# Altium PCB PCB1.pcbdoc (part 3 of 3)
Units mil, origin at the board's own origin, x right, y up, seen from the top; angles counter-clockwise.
Board outline 8664.15 x 6684.89 mil, 2 copper layers (Top Layer, Bottom Layer); 317 components, 306 nets, 1008 pads, 181 vias.
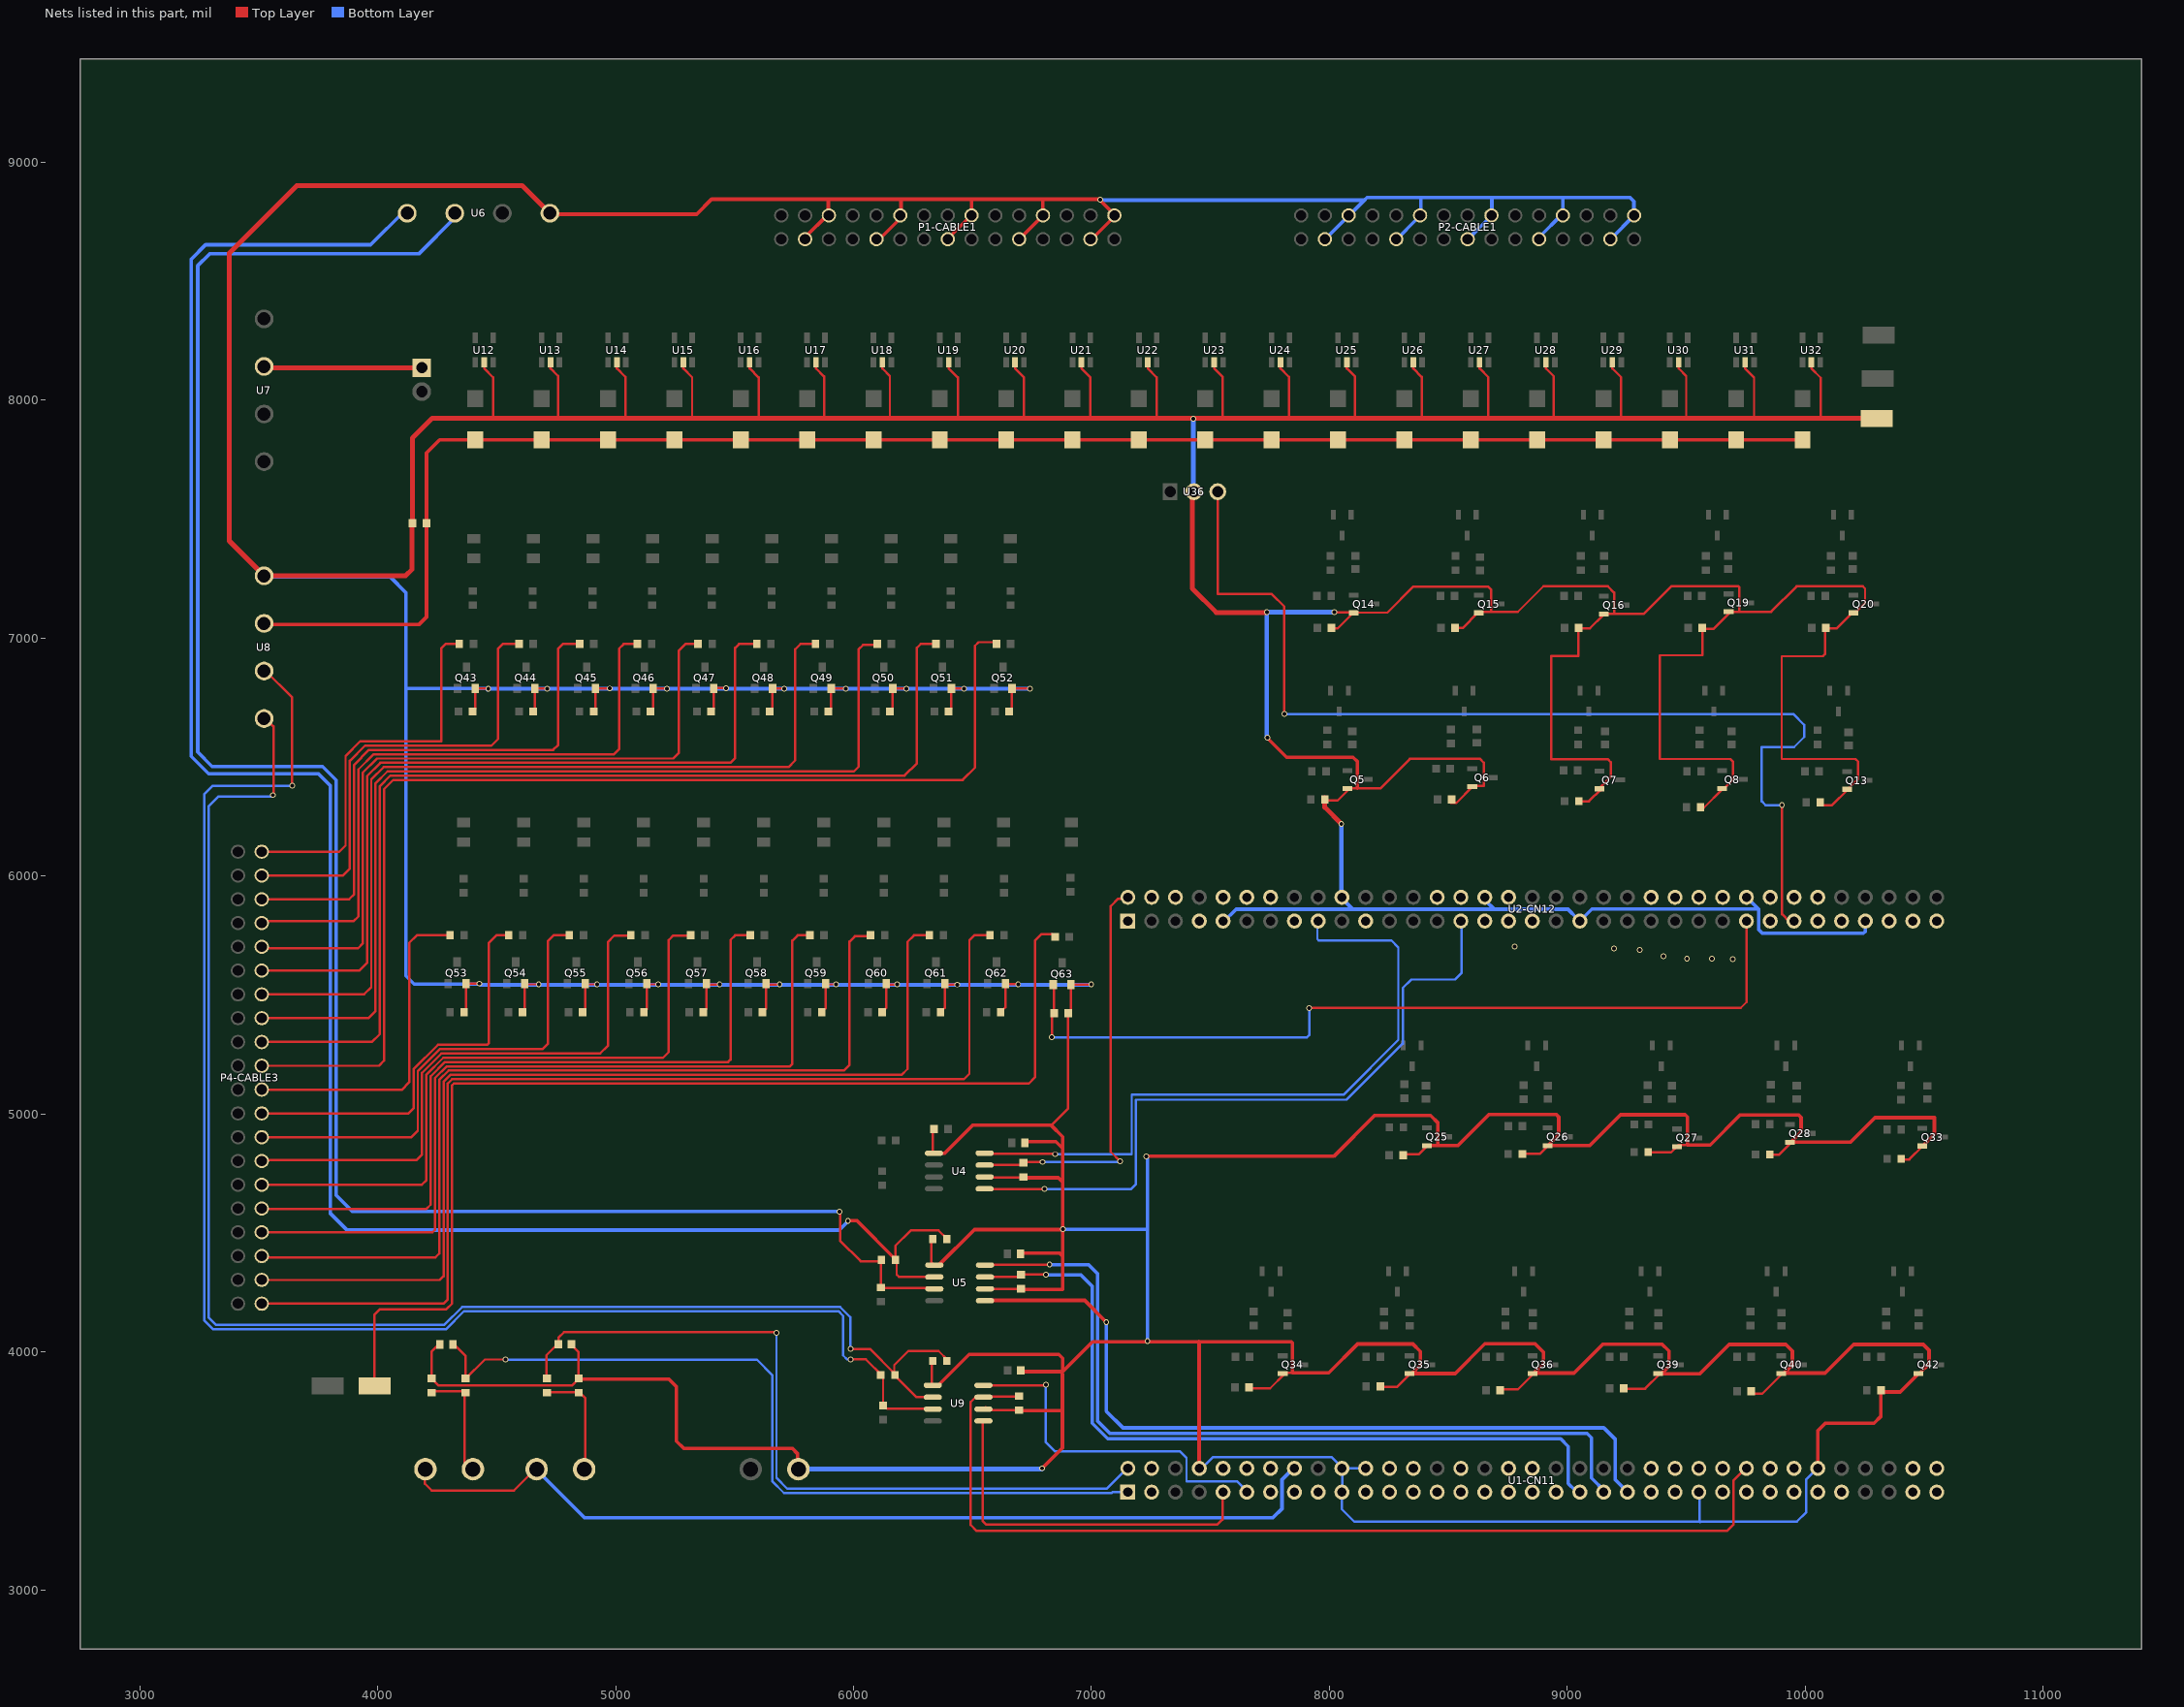
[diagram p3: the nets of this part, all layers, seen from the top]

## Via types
v1: diameter 24.02, hole 16, Top Layer to Bottom Layer, 181 vias

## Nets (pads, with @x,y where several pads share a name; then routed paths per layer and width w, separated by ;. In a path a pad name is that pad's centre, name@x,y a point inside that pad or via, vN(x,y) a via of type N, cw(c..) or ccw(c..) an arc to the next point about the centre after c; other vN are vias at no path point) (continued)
DO21: Q63.1 R126.2 U2-CN12.53 | length 3607.6
  Top Layer w10: v1@6833.62,5324.44 6834.26,5325.09 R126.2@6834.26,5427.61 ; Q63.1@6839.51,5544.34 6843.32,5540.53 R126.2@6843.32,5424.26 ; v1(7915.05,5445.54) 7915.71,5446.2 9729.52,5446.2 9754.1,5470.78 U2-CN12.53@9754.1,5796.94 ; U2-CN12.53@9749.58,5814.58 U2-CN12.53@9753.9,5810.26
  Bottom Layer w10: v1(6834.26,5323.16) 6835.39,5322.04 7905.61,5322.04 7916.92,5333.35 7916.92,5443.67 v1(7915.05,5445.54)
GND: C22.2 C23.2 C24.2 C25.2 C26.2 CN3.1 P1-CABLE1.3 P1-CABLE1.6 P1-CABLE1.9 P1-CABLE1.12 P1-CABLE1.15 P1-CABLE1.18 P1-CABLE1.21 P1-CABLE1.24 P1-CABLE1.27 P1-CABLE1.30 P2-CABLE1.3 P2-CABLE1.6 P2-CABLE1.9 P2-CABLE1.12 P2-CABLE1.15 P2-CABLE1.18 P2-CABLE1.21 P2-CABLE1.24 P2-CABLE1.27 P2-CABLE1.30 Q5.2 Q6.2 Q7.2 Q8.2 Q13.2 Q14.2 Q15.2 Q16.2 Q19.2 Q20.2 Q25.2 Q26.2 Q27.2 Q28.2 Q33.2 Q34.2 Q35.2 Q36.2 Q39.2 Q40.2 Q42.2 Q43.2 Q44.2 Q45.2 Q46.2 Q47.2 Q48.2 Q49.2 Q50.2 Q51.2 Q52.2 Q53.2 Q54.2 Q55.2 Q56.2 Q57.2 Q58.2 Q59.2 Q60.2 Q61.2 Q62.2 Q63.2 R9.1 R10.1 R11.1 R12.1 R21.1 R22.1 R23.1 R24.1 R29.1 R30.1 R39.1 R40.1 R41.1 R42.1 R51.1 R52.1 R53.1 R54.1 R59.1 R60.1 R63.1 R74.1 R75.1 R76.1 R77.1 R78.1 R89.1 R90.1 R91.1 R92.1 R93.1 R104.1 R105.1 R106.1 R107.1 R108.1 R119.1 R120.1 R121.1 R122.1 R123.1 R126.1 R129.1 R130.1 R133.1 R134.1 R136.1 R138.1 R141.1 R142.1 R143.1 U1-CN11.8 U1-CN11.19 U1-CN11.20 U1-CN11.22 U1-CN11.49 U1-CN11.60 U2-CN12.9 U2-CN12.20 U2-CN12.32 U2-CN12.39 U2-CN12.54 U2-CN12.63 U3.2 U4.2 U4.5 U5.2 U5.5 U6.4 U8.4 U9.2 U9.5 U12.2 U13.2 U14.2 U15.2 U16.2 U17.2 U18.2 U19.2 U20.2 U21.2 U22.2 U23.2 U24.2 U25.2 U26.2 U27.2 U28.2 U29.2 U30.2 U31.2 U32.2 U36.2 | length 72804.7
  Top Layer w10: U8.4@3522.95,7262.24 U8.4@3523.74,7261.45 ; R141.1@4225.92,3890.5 4225.92,4000.31 C25.2@4262.95,4037.34 ; R141.1@4229.24,3885.15 4256.05,3858.34 4815.97,3858.34 R142.1@4845.97,3888.34 ; R104.1@4363.26,5428.19 4371,5435.93 Q53.2@4371,5548.27 v1@4427.85,5548.27 ; R74.1@4398.7,6691.97 4410.37,6703.64 Q43.2@4410.37,6788.43 4463.95,6788.43 v1@4465.74,6786.64 ; U12.2@4447.78,8160.48 4447.78,8133.82 4485.35,8096.25 4485.35,7924.26 ; R105.1@4608.64,5428.19 4617.72,5437.27 Q54.2@4617.72,5548.27 4621.14,5544.85 v1@4678.12,5544.85 ; R75.1@4653.28,6691.97 4661.03,6699.71 Q44.2@4661.03,6788.43 4709.75,6788.43 v1@4711.8,6790.48 ; U13.2@4726.72,8160.48 4726.72,8133.82 4758.32,8102.22 4758.32,7924.26 ; C26.2@4818.52,4024.65 4844.38,3998.79 R142.1@4844.38,3892.49 ; R106.1@4861.9,5428.19 4872.31,5438.6 Q55.2@4872.31,5548.27 4875.73,5544.85 v1@4921.05,5544.85 ; R76.1@4907.88,6691.97 4915.62,6699.71 Q45.2@4915.62,6788.43 4969.53,6788.43 v1@4970.36,6787.6 ; U14.2@5005.66,8160.48 5005.66,8133.82 5041.55,8097.93 5041.55,7924.26 ; R107.1@5119.1,5428.19 5130.84,5439.93 Q56.2@5130.84,5548.27 5134.12,5544.99 v1@5179.78,5544.99 ; R77.1@5146.72,6691.97 5158.4,6703.65 Q46.2@5158.4,6788.43 5212.71,6788.43 v1@5213.54,6787.6 ; U15.2@5284.59,8160.48 5284.59,8133.82 5321.79,8096.63 5321.79,7924.26 ; R108.1@5368.43,5428.19 5381.5,5441.26 Q57.2@5381.5,5548.27 5385.17,5544.6 v1@5437.94,5544.6 ; R78.1@5401.32,6691.97 5412.99,6703.65 Q47.2@5412.99,6788.43 5416.01,6791.44 v1@5463.44,6791.44 ; U16.2@5563.53,8160.48 5563.53,8133.82 5601.27,8096.08 5601.27,7924.26 ; R119.1@5617.75,5428.19 5632.15,5442.6 Q58.2@5632.15,5548.27 5635.99,5544.44 v1(5689.64,5544.44) ; R89.1@5648.04,6691.97 5659.71,6703.65 Q48.2@5659.71,6788.43 5707.71,6788.43 v1@5709.5,6786.64 ; U17.2@5842.47,8160.48 5842.47,8133.82 5876.17,8100.12 5876.17,7924.26 ; R120.1@5867.07,5428.19 5882.81,5443.93 Q59.2@5882.81,5548.27 ; Q59.2@5888.15,5542.93 5890.05,5544.83 v1@5926.83,5544.83 ; R90.1@5894.75,6691.97 5906.43,6703.65 Q49.2@5906.43,6788.43 5967.71,6788.43 v1@5968.49,6789.2 ; R121.1@6120.33,5428.19 6137.4,5445.26 Q60.2@6137.4,5545.65 ; U18.2@6121.4,8160.48 6121.4,8133.82 6152.99,8102.24 6152.99,7924.26 ; Q60.2@6137.93,5546.17 Q60.2@6137.4,5545.65 ; R91.1@6153.28,6691.97 6164.96,6703.65 Q50.2@6164.96,6788.43 6165.63,6789.09 6220.31,6789.09 v1@6223.73,6785.67 ; v1@6182.78,5544.7 6138.35,5544.7 Q60.2@6137.4,5545.65 ; R134.1@6327.01,4471.34 6327.01,4377.49 U5.5@6341.37,4363.12 ; U9.5@6328.46,3863.83 R138.1@6328.46,3960.56 ; U4.5@6332.9,4837.31 6332.9,4933.08 R133.1@6341.83,4942.02 ; R122.1@6365.72,5428.19 6384.12,5446.59 Q61.2@6384.12,5545.41 ; Q61.2@6384.42,5545.71 Q61.2@6384.12,5545.41 ; R92.1@6400,6691.97 6411.68,6703.65 Q51.2@6411.68,6788.43 v1@6460.05,6788.43 ; U19.2@6400.34,8160.48 6400.34,8133.82 6438.46,8095.71 6438.46,7924.26 ; v1@6431.43,5544.28 6385.26,5544.28 Q61.2@6384.12,5545.41 ; U9.2@6555.9,3767.79 6547.28,3759.17 6551.11,3755.34 R136.1@6695.72,3755.34 ; U4.2@6564.01,4732.61 6718.13,4732.61 6722.74,4732.61 R129.1@6725.29,4735.16 ; U5.2@6569.16,4263.91 6696.21,4263.91 R130.1@6696.85,4264.55 ; R123.1@6618.98,5428.19 6638.72,5447.93 Q62.2@6638.72,5548.27 ; Q62.2@6644.47,5542.52 6647.12,5545.18 v1@6693.37,5545.18 ; R93.1@6654.6,6691.97 6666.28,6703.65 Q52.2@6666.28,6788.43 v1@6740.98,6788.43 ; U20.2@6679.28,8160.48 6679.28,8133.82 6715.5,8097.6 6715.5,7924.26 ; 6830.7,4951.63 6831.23,4952.16 6902.64,5023.57 R126.1@6902.64,5424.26 6914.32,5435.94 Q63.2@6914.32,5544.34 v1@6999.35,5544.34 ; 6876.91,3910.77 6879.46,3913.33 6879.46,3916.85 ; 6879.06,4855.75 6879.06,4835.38 6879.46,4834.98 6880.02,4834.42 ; U21.2@6958.22,8160.48 6958.22,8133.82 6995.94,8096.1 6995.94,7924.26 ; U22.2@7237.15,8160.48 7237.15,8133.82 7274.68,8096.3 7274.68,7924.26 ; U23.2@7516.09,8160.48 7516.09,8133.82 7552.14,8097.77 7552.14,7924.26 ; R52.1@7668.77,3849.47 7671.62,3846.62 7751.13,3846.62 Q34.2@7810.73,3906.21 ; U24.2@7795.03,8160.48 7795.03,8133.82 7830.24,8098.61 7830.24,7924.26 ; Q34.2@7806.09,3912.44 7845.23,3912.44 ; R9.1@7981.27,6317.81 8034.61,6317.81 Q5.2@8079.31,6362.5 ; R22.1@8007.85,7041.06 8035.41,7041.06 Q14.2@8095.64,7101.3 ; v1(8022.01,7108.97) 8101.39,7108.97 8102.78,7107.58 8244.18,7107.58 8353.99,7217.39 8667.16,7217.39 8681.2,7203.35 8681.2,7110.45 ; U25.2@8073.96,8160.48 8073.96,8133.82 8108.34,8099.45 8108.34,7924.26 ; Q5.2@8078.48,6367.27 8081.04,6369.82 8117.67,6369.82 8216.31,6369.82 8338.89,6492.4 8633.92,6492.4 8649.88,6476.44 8649.88,6378.12 8648.61,6379.4 Q6.2@8603.28,6379.4 ; R53.1@8211.54,3852.39 8284.59,3852.39 Q35.2@8341.27,3909.08 ; R39.1@8322.09,4830.55 8375.91,4830.55 Q25.2@8408.38,4863.02 ; Q35.2@8340.02,3909.08 Q35.2@8341.27,3909.08 ; Q35.2@8344.18,3911.98 Q35.2@8341.27,3909.08 ; Q35.2@8345.31,3906.67 8347.71,3909.08 Q35.2@8341.27,3909.08 ; U26.2@8352.9,8160.48 8352.9,8133.82 8388.36,8098.36 8388.36,7924.26 ; R10.1@8510.4,6307.71 8534.42,6307.71 Q6.2@8602.67,6375.96 ; R23.1@8526.25,7042.99 8560.85,7042.99 Q15.2@8624.93,7107.06 ; Q15.2@8621.43,7109.18 8622.71,7110.45 8681.2,7110.45 ; U27.2@8631.84,8160.48 8631.84,8133.82 8669.02,8096.64 8669.02,7924.26 ; R54.1@8728.65,3842.77 8793.05,3842.77 Q36.2@8860.33,3910.06 ; R40.1@8819.28,4832.37 8884.64,4832.37 Q26.2@8915.4,4863.12 ; Q36.2@8857.99,3910.89 8860.87,3910.89 Q36.2@8860.01,3910.04 ; U28.2@8910.78,8160.48 8910.78,8133.82 8943.85,8100.75 8943.85,7924.26 ; R24.1@9040.4,7045.08 9046.78,7038.69 9046.78,6925.69 8932.98,6925.69 8932.98,6491.95 9169.61,6491.95 9182.68,6478.88 9182.68,6416.82 Q7.2@9133.53,6367.67 ; R24.1@9045.28,7041.06 9095.26,7041.06 Q16.2@9152.29,7098.09 ; R11.1@9050.21,6314.45 9091.22,6314.45 9143.45,6366.67 Q7.2@9143.45,6360.9 ; Q16.2@9157.08,7102.15 9157.72,7101.52 9197.3,7101.52 ; U29.2@9189.71,8160.48 9189.71,8133.82 9226.43,8097.1 9226.43,7924.26 ; R59.1@9239.03,3845.66 9327.46,3845.66 Q39.2@9387.05,3905.25 ; R41.1@9336.86,4838.88 9437.09,4838.88 Q27.2@9465.18,4866.97 ; U30.2@9468.65,8160.48 9468.65,8133.82 9500.26,8102.21 9500.26,7924.26 ; Q27.2@9468.7,4869.85 9505.42,4869.85 ; R12.1@9552.36,6287.61 9574.47,6287.61 Q8.2@9653.28,6366.43 ; R29.1@9569.95,7040.17 9616.09,7040.17 Q19.2@9681.45,7105.53 ; R29.1@9571.26,7044.79 9569.34,7042.88 9569.34,6928.31 9389.2,6928.31 9389.2,6492.17 9685.01,6492.17 9697.59,6479.59 9697.59,6405.98 Q8.2@9653.54,6361.92 ; Q19.2@9678.68,7113.01 9680.6,7111.09 9724.01,7111.09 ; U31.2@9747.59,8160.48 9747.59,8133.82 9785.57,8095.84 9785.57,7924.26 ; R60.1@9772.48,3824.51 9819.58,3824.51 Q40.2@9903.2,3908.13 ; R42.1@9850.25,4829.28 9890.83,4829.28 Q28.2@9942.09,4880.54 ; Q28.2@9937.95,4879.42 9944.17,4885.65 Q28.2@9943.21,4886.61 ; U32.2@10026.52,8160.48 10026.52,8133.82 10065.89,8094.45 10065.89,7924.26 ; R21.1@10068.44,6297.94 10113.3,6297.94 Q13.2@10179.94,6364.58 ; R30.1@10084.24,7048.45 10084.24,6934.18 10074.24,6924.18 9901.59,6924.18 9901.59,6492.17 10212.03,6492.17 10223.34,6480.85 10223.34,6408.85 Q13.2@10177.38,6362.88 ; R30.1@10087.07,7042.16 10133.2,7042.16 Q20.2@10196.64,7105.59 ; Q20.2@10209.86,7105.98 10252,7148.12 10252,7208.49 10242.78,7217.71 9964.07,7217.71 9857.45,7111.09 9724.01,7111.09 ; R63.1@10316.03,3831.72 R63.1@10318.38,3831.72 ; R51.1@10401.37,4809.15 10437.9,4809.15 Q33.2@10495.57,4866.82 ; 8681.2,7110.45 8792.53,7110.45 8900.43,7218.35 9170.49,7218.35 9197.3,7191.53 9197.3,7101.52 ; 9197.3,7101.52 9321.16,7101.52 9438.63,7218.99 9718.27,7218.99 9724.01,7213.24 9724.01,7111.09
  Top Layer w15: U6.4@4716.61,8780.8 4718.05,8782.24 5340.89,8782.24 5403.85,8845.2 5892.18,8845.2 ; R142.1@4850.79,3885.96 5223.8,3885.96 5255.88,3853.87 5255.88,3624.93 5286.95,3593.87 5743.3,3593.87 5764.4,3572.77 5764.4,3510.55 U3.2@5759.61,3505.77 ; P1-CABLE1.3@5785.01,8680.84 5792.22,8680.84 P1-CABLE1.6@5896.03,8784.65 ; 5891.22,8846.16 5892.18,8845.2 ; P1-CABLE1.6@5894.1,8785.61 5894.1,8843.28 5892.18,8845.2 ; P1-CABLE1.9@6092.11,8669.3 6100.76,8669.3 P1-CABLE1.12@6194.47,8763.02 ; P1-CABLE1.12@6193.99,8777.92 6199.76,8783.68 6199.76,8837.51 ; U4.5@6354.3,4839.36 6358.97,4834.69 6383.04,4834.69 6501.52,4953.17 6830.22,4953.17 6831.23,4952.16 6879.06,4904.33 6879.06,4855.75 ; U9.5@6355.79,3854.67 6355.79,3859.01 6486.28,3989.5 6862.61,3989.5 6879.46,3972.64 6879.46,3916.85 ; U5.5@6357.25,4363.24 6509.19,4515.19 ; P1-CABLE1.15@6386.61,8669.3 6492.58,8775.27 P1-CABLE1.18@6502.29,8775.27 ; P1-CABLE1.18@6504.45,8777.44 P1-CABLE1.18@6502.29,8775.27 ; P1-CABLE1.18@6507.33,8770.23 P1-CABLE1.18@6502.29,8775.27 ; 6510.41,4513.97 v1@6879.46,4513.97 ; R136.1@6682.96,3752.49 6878.47,3752.49 ; P1-CABLE1.21@6687.55,8693.81 6713.51,8693.81 P1-CABLE1.24@6796.2,8776.51 ; C23.2@6708.52,4415.14 6866.53,4415.14 6879.46,4402.21 ; R130.1@6709.76,4261.79 6879.46,4261.79 6879.46,4402.21 ; R129.1@6716.66,4734.08 6718.13,4732.61 6718.74,4732 6861.07,4732 6877.35,4715.72 ; C22.2@6718.38,4884.27 6850.54,4884.27 6879.06,4855.75 ; 6720.7,3916.85 6879.46,3916.85 ; v1(6792.28,3510.56) 6878.23,3596.51 6878.23,3752.25 6878.47,3752.49 ; P1-CABLE1.24@6796.2,8774.86 P1-CABLE1.24@6796.2,8776.51 ; P1-CABLE1.24@6798.57,8778.88 P1-CABLE1.24@6796.2,8776.51 ; 6799.09,8843.11 6796.2,8840.22 P1-CABLE1.24@6796.2,8776.51 ; 6878.47,3906.18 6878.47,3752.49 ; v1@6880.06,4513.97 v1@6879.46,4513.97 ; P1-CABLE1.27@7006.18,8679.4 7006.18,8680.84 P1-CABLE1.30@7099.9,8774.55 ; P1-CABLE1.30@7101.34,8775.99 7032.14,8845.2 6496.23,8845.2 ; v1@7229.99,4042.44 7005.05,4042.44 6879.46,3916.85 ; v1(7230.57,4822.17) 8018.73,4822.17 8190.63,4994.07 8425.25,4994.07 8456.86,4962.46 8456.86,4871.48 8458.77,4869.57 ; v1(7235.91,4044.85) 7238.45,4042.3 7452.66,4042.3 ; 7451.7,4043.52 7452.66,4042.56 7452.66,4042.3 ; U1-CN11.8@7452.66,3529.33 7452.66,4042.3 ; v1@7740.89,6578.76 7820.17,6499.48 8100.07,6499.48 8117.67,6481.89 8117.67,6369.82 ; Q25.2@8408.89,4865.38 8410.8,4867.29 8541.04,4867.29 8671.29,4997.53 8954.15,4997.53 8964.82,4986.87 8964.82,4912.16 Q26.2@8923.15,4870.48 ; Q26.2@8913.59,4866 8914.54,4866.96 9093.63,4866.96 9223.87,4997.2 9495.42,4997.2 9505.42,4987.2 9505.42,4869.85 9600.85,4869.85 9726.73,4995.72 9972.96,4995.72 9982.96,4985.72 9982.96,4924.43 9944.17,4885.65 9948,4881.82 10191.25,4881.82 10293.72,4984.29 10543.67,4984.29 10543.67,4914.38 Q33.2@10493.87,4864.58 ; Q39.2@9381.22,3908.53 9558.56,3908.53 9681.11,4031.08 9919,4031.08 9946.4,4003.68 9946.4,3946.01 Q40.2@9911.79,3911.41 ; Q39.2@9398.81,3910.89 9427.53,3939.62 9427.53,4003.27 9398.81,4032 9149.86,4032 9028.75,3910.89 8860.87,3910.89 8900.38,3950.41 8900.38,3998.46 8864.82,4034.03 8654.32,4034.03 8529.37,3909.08 8347.71,3909.08 8383.01,3944.37 8383.01,4001.61 8351.07,4033.55 8118.95,4033.55 7997.84,3912.44 7845.23,3912.44 7845.23,4037.99 7840.92,4042.3 7452.66,4042.3 ; Q40.2@9914.2,3910.93 10084.32,3910.93 10204.47,4031.08 10496.67,4031.08 10520.7,4007.05 10520.7,3949.38 Q42.2@10479.37,3908.05 ; U1-CN11.60@10053.28,3518.01 10053.28,3668.27 10085.34,3700.33 10289.61,3700.33 10318.89,3729.6 10318.89,3831.21 R63.1@10318.38,3831.72 ; R63.1@10312.95,3837.14 R63.1@10318.38,3831.72 ; Q42.2@10473.66,3905.73 10399.65,3831.72 R63.1@10318.38,3831.72 ; 5892.18,8845.2 6496.23,8845.2 ; 6496.23,8845.2 6496.23,8781.33 P1-CABLE1.18@6502.29,8775.27 ; 6879.06,4855.75 6879.46,4855.34 6879.46,4834.98 v1@6879.46,4513.97 ; 6879.46,4402.21 v1@6879.46,4513.97
  Top Layer w20: U8.4@3522.59,7262.23 U8.4@3522.95,7262.24 ; R143.1@4144.63,7475.44 4144.63,7289.61 4117.26,7262.24 U8.4@3522.95,7262.24 ; R143.1@4146.47,7483.31 4146.47,7841.88 4228.85,7924.26 4485.35,7924.26 4758.32,7924.26 5041.55,7924.26 5321.79,7924.26 5601.27,7924.26 5876.17,7924.26 6152.99,7924.26 6438.46,7924.26 6715.5,7924.26 6995.94,7924.26 7274.68,7924.26 7552.14,7924.26 7830.24,7924.26 8108.34,7924.26 8388.36,7924.26 8669.02,7924.26 8943.85,7924.26 9226.43,7924.26 9500.26,7924.26 9785.57,7924.26 10065.89,7924.26 10287.9,7924.26 CN3.1@10287.99,7924.35 ; U6.4@4725.05,8784.93 4607.65,8902.33 3660.25,8902.33 3376.3,8618.39 3376.3,7408.88 U8.4@3522.95,7262.24 ; U36.2@7424.18,7604.53 7424.18,7208.94 7524.9,7108.23 7736.04,7108.23 v1(7737.25,7109.44) ; R9.1@7981.19,6329.02 7981.19,6288.93 v1(8050.8,6219.32)
  Bottom Layer w10: U1-CN11.8@7451.66,3498.62 7509.91,3556.87 8011.06,3556.87 U1-CN11.20@8047.46,3520.46 ; U1-CN11.20@8045.47,3508.74 8053.97,3500.24 U1-CN11.19@8053.97,3405.59 ; U1-CN11.19@8052.17,3392.39 8052.17,3339.61 8105.25,3286.52 9557.94,3286.52 ; U1-CN11.20@8057.61,3509.95 8141.33,3509.95 U1-CN11.22@8151.04,3500.24 ; U1-CN11.49@9545.62,3409.68 9556.94,3398.36 9556.94,3287.52 9557.94,3286.52 ; 9559.09,3285.37 9557.94,3286.52 ; U1-CN11.60@10045.56,3504.94 10003.69,3463.08 10003.69,3324.69 9965.52,3286.52 9557.94,3286.52
  Bottom Layer w15: U8.4@3522.37,7266.01 3530.36,7258.01 4052.53,7258.01 4119.13,7191.41 4119.13,6788.33 ; v1@4461.19,6782.54 4466.62,6787.97 5216.42,6787.97 6464.03,6787.97 v1(6741.8,6787.97) ; v1(4465.09,6786.9) 4463.66,6788.33 4119.13,6788.33 ; v1(6880.11,4515.3) 7234.53,4515.3 7235.88,4513.95 ; v1@6999.71,5543.19 4432.71,5543.19 v1(4428.01,5547.89) 4426.3,5546.18 4153.81,5546.18 4119.13,5580.86 4119.13,6788.33 ; v1@7038.38,8841.13 8147.53,8841.13 ; v1@7231.05,4821.21 7235.91,4816.35 v1(7235.91,4044.85) ; U2-CN12.9@7554.2,5806.68 7608.27,5860.74 8098.36,5860.74 ; P2-CABLE1.3@7978,8672.81 P2-CABLE1.6@8083.73,8778.54 ; U2-CN12.20@8049.69,5909.41 8098.36,5860.74 ; P2-CABLE1.6@8080.85,8781.66 8088.06,8781.66 8147.53,8841.13 ; P2-CABLE1.9@8287.02,8680.74 8364.88,8758.59 P2-CABLE1.12@8364.88,8775.89 ; P2-CABLE1.12@8385.06,8776.7 8385.06,8851.03 ; P2-CABLE1.15@8581.14,8676.41 8667.65,8762.92 P2-CABLE1.18@8679.18,8762.92 ; U2-CN12.32@8656.33,5913.05 8656.33,5897.68 8693.27,5860.74 ; P2-CABLE1.18@8683.66,8772.85 8683.66,8852.31 ; P2-CABLE1.21@8889.68,8693.71 8970.42,8774.45 P2-CABLE1.24@8971.86,8774.45 ; P2-CABLE1.24@8982.27,8776.7 8982.27,8852.31 ; U2-CN12.39@9040.67,5818.81 U2-CN12.39@9043.12,5821.26 ; U2-CN12.39@9056.49,5807.89 U2-CN12.39@9043.12,5821.26 ; P2-CABLE1.27@9185.24,8680.74 9280.39,8775.89 9280.39,8836.15 9264.24,8852.31 8982.27,8852.31 ; U2-CN12.54@9757.16,5908.53 9804.19,5861.5 ; U2-CN12.63@10252.25,5806.6 U2-CN12.63@10252.62,5806.97 ; U2-CN12.63@10252.62,5807.38 U2-CN12.63@10252.62,5806.97 ; 8098.36,5860.74 8693.27,5860.74 ; 8147.53,8841.13 8158.7,8852.31 8683.66,8852.31 ; 8683.66,8852.31 8982.27,8852.31 ; 8693.27,5860.74 9003.64,5860.74 U2-CN12.39@9043.12,5821.26 ; U2-CN12.39@9043.12,5821.26 9063.62,5821.26 9103.86,5861.5 9804.19,5861.5 ; 9804.19,5861.5 9804.89,5860.8 9804.89,5774.65 9819.89,5759.65 10245.34,5759.65 10252.62,5766.93 U2-CN12.63@10252.62,5806.97
  Bottom Layer w20: U3.2@5766.08,3505.21 5768,3507.13 v1@6792.8,3507.13 ; U36.2@7428.08,7616.16 7429.03,7617.11 v1(7429.03,7922.61) ; v1(7740.08,6581.19) 7736.88,6584.39 7736.88,7108.97 v1(8022.01,7108.97) ; v1(8050.8,6219.32) 8050.8,5912.39 U2-CN12.20@8051.78,5911.41
  other v1: 5178.69,5544.24 5437.14,5544.39 5926.64,5544.26 6436.44,5543.72 6692.11,5544.47 6999.62,5544.13 4676.92,5545.38 4921.72,5545.17 6183.11,5544.69 9696.65,5650.59 9608.88,5652.15 9503.25,5652.92 9403.83,5663.02 9304.41,5690.21 9197.22,5695.64 8778.57,5704.19 4712.62,6787.66 5216.42,6787.9 5709.1,6787.62 5968.06,6788.35 6222.72,6787.69 6464.03,6787.92 4975.96,6788.85 5464.66,6789.23 7037.39,8843.95
IOREF: U1-CN11.12
LED1-: P4-CABLE3.2 R69.1 | length 1641.8
  Top Layer w10: P4-CABLE3.2@3512.95,6102.6 3514.14,6101.42 3837.84,6101.42 3865.1,6128.68 3865.1,6504.86 3926.61,6566.37 4266.68,6566.37 4266.68,6956.5 4285.61,6975.43 R69.1@4343.31,6975.43
LED2-: P4-CABLE3.4 R70.1 | length 1972.3
  Top Layer w10: P4-CABLE3.4@3512.95,6002.6 3513.35,6003 3854.76,6003 3883.1,6031.34 3883.1,6484.8 3946.67,6548.37 4478.41,6548.37 4506.84,6576.79 4506.84,6956.65 4525.62,6975.43 R70.1@4594.19,6975.43
LED3-: P4-CABLE3.6 R71.1 | length 2336.4
  Top Layer w10: P4-CABLE3.6@3512.95,5902.6 3880.2,5902.6 3901.1,5923.51 3901.1,6467.85 3963.62,6530.37 4737.7,6530.37 4758.8,6551.47 4758.8,6956.19 4778.06,6975.44 R71.1@4849.02,6975.43
LED4-: P4-CABLE3.8 R72.1 | length 2674.3
  Top Layer w10: P4-CABLE3.8@3512.95,5802.6 3520.44,5810.08 3898.41,5810.08 3919.1,5830.77 3919.1,6448.57 3982.91,6512.37 4993.88,6512.37 5014.71,6533.19 5014.71,6955.77 5034.37,6975.43 R72.1@5092.03,6975.43
LED5-: P4-CABLE3.10 R73.1 | length 3039.5
  Top Layer w10: P4-CABLE3.10@3512.95,5702.6 3519.65,5695.91 3917,5695.91 3937.1,5716.01 3937.1,6433.94 3997.53,6494.37 5243.08,6494.37 5266.68,6517.97 5266.68,6948.59 5293.52,6975.43 R73.1@5346.85,6975.43
LED6-: P4-CABLE3.12 R84.1 | length 3380.1
  Top Layer w10: P4-CABLE3.12@3512.95,5602.6 3922.73,5602.6 3955.1,5634.98 3955.1,6420.1 4011.37,6476.37 5482.17,6476.37 5502.9,6497.1 5502.9,6959.16 5519.18,6975.44 R84.1@5593.8,6975.43
LED7-: P4-CABLE3.14 R85.1 | length 3722.8
  Top Layer w10: P4-CABLE3.14@3512.95,5502.6 3513.35,5503 3943.13,5503 3973.1,5532.97 3973.1,6406.25 4025.22,6458.37 5726.7,6458.37 5754.87,6486.53 5754.87,6953.3 5777,6975.43 R85.1@5840.75,6975.43
LED8-: P4-CABLE3.16 R86.1 | length 4088.3
  Top Layer w10: P4-CABLE3.16@3512.95,5402.6 3961.57,5402.6 3991.1,5432.14 3991.1,6390.08 4041.4,6440.37 6002.3,6440.37 6022.58,6460.65 6022.58,6954.26 6039.83,6971.5 6095.58,6971.5 R86.1@6099.51,6975.43
LED9-: P4-CABLE3.18 R87.1 | length 4421.1
  Top Layer w10: P4-CABLE3.18@3512.95,5302.6 3975.75,5302.6 4009.1,5335.96 4009.1,6377.78 4053.69,6422.37 6214.87,6422.37 6266.68,6474.18 6266.68,6959.68 6282.43,6975.43 R87.1@6346.46,6975.43
LED10-: P4-CABLE3.20 R88.1 | length 4797.6
  Top Layer w10: P4-CABLE3.20@3512.95,5202.6 4005.07,5202.6 4027.1,5224.63 4027.1,6365.49 4065.98,6404.37 6459.42,6404.37 6510.77,6455.72 6510.77,6967.98 6526.1,6983.31 6593.41,6983.31 R88.1@6601.29,6975.43
LED11-: P4-CABLE3.22 R99.1 | length 1403.6
  Top Layer w10: P4-CABLE3.22@3512.95,5102.6 3514.14,5101.42 4100.79,5101.42 4132.82,5133.45 4132.82,5719.07 4164.77,5751.02 R99.1@4303.94,5751.02
LED12-: P4-CABLE3.24 R100.1 | length 1691
  Top Layer w10: P4-CABLE3.24@3512.95,5002.6 4130.13,5002.6 4150.82,5023.29 4150.82,5188.01 4253.21,5290.4 4459.43,5290.4 4467.47,5298.43 4467.47,5719.34 4499.15,5751.02 R100.1@4550.89,5751.02
LED13-: P4-CABLE3.26 R101.1 | length 2044.4
  Top Layer w10: P4-CABLE3.26@3512.95,4902.6 4141.98,4902.6 4168.82,4929.45 4168.82,5180.55 4260.67,5272.4 4693.09,5272.4 4715.5,5294.81 4715.5,5726.9 4739.63,5751.03 R101.1@4805.71,5751.02
LED14-: P4-CABLE3.28 R102.1 | length 2401
  Top Layer w10: P4-CABLE3.28@3512.95,4802.6 3516.5,4806.15 4163.19,4806.15 4186.82,4829.77 4186.82,5173.1 4268.12,5254.4 4935.49,5254.4 4967.47,5286.38 4967.47,5722.63 4995.05,5750.21 5063.65,5750.21 R102.1@5064.47,5751.02
LED15-: P4-CABLE3.30 R103.1 | length 2772
  Top Layer w10: P4-CABLE3.30@3512.95,4702.6 4185.48,4702.6 4204.82,4721.94 4204.82,5165.64 4275.58,5236.4 5198.85,5236.4 5223.37,5260.92 5223.37,5731.15 5242.33,5750.1 5314.43,5750.1 R103.1@5315.36,5751.02
LED16-: P4-CABLE3.32 R114.1 | length 3140.4
  Top Layer w10: P4-CABLE3.32@3512.95,4602.6 3514.14,4601.42 4205.05,4601.42 4222.82,4619.19 4222.82,5158.18 4283.04,5218.4 5473.21,5218.4 5483.21,5228.4 5483.21,5731.48 5502.76,5751.02 R114.1@5566.24,5751.02
LED17-: P4-CABLE3.34 R115.1 | length 3498.4
  Top Layer w10: P4-CABLE3.34@3512.95,4502.6 4230.82,4502.6 4240.82,4512.6 4240.82,5150.73 4290.49,5200.4 5733.06,5200.4 5743.06,5210.4 5743.06,5728.4 5765.62,5750.96 R115.1@5817.13,5751.02
LED18-: P4-CABLE3.36 R116.1 | length 3853.7
  Top Layer w10: P4-CABLE3.36@3512.95,4402.6 3518.86,4396.7 4242.3,4396.7 4258.82,4413.21 4258.82,5143.27 4297.95,5182.4 5959.23,5182.4 5983.21,5206.38 5983.21,5724.67 6005.64,5747.09 6068.02,5747.09 R116.1@6071.95,5751.02
LED19-: P4-CABLE3.38 R117.1 | length 4198.5
  Top Layer w10: P4-CABLE3.38@3512.95,4302.6 3513.35,4302.21 4260.99,4302.21 4276.82,4318.04 4276.82,5135.82 4305.4,5164.4 6202.37,5164.4 6227.31,5189.34 6227.31,5724.1 6254.24,5751.02 R117.1@6318.9,5751.02
LED20-: P4-CABLE3.40 R118.1 | length 4562.4
  Top Layer w10: P4-CABLE3.40@3512.95,4202.6 4276.66,4202.6 4294.82,4220.76 4294.82,5128.36 4312.86,5146.4 6464.57,5146.4 6487.15,5168.98 6487.15,5729.95 6508.23,5751.03 R118.1@6573.73,5751.02
LED21-: CN5.1 R125.1 | length 4700.1
  Top Layer w10: CN5.1@3987.15,3857.33 3987.15,4157.08 4009.67,4179.6 4288.84,4179.6 4312.82,4203.59 4312.82,5120.9 4320.32,5128.4 6737.26,5128.4 6762.74,5153.88 6762.74,5728.64 6789.07,5754.97 6837.29,5754.97 R125.1@6847.42,5744.84
MCU_3V3: U1-CN11.16 U10.1 U11.1 | length 4016.4
  Top Layer w10: U10.1@4198.91,3519.01 4198.91,3445.27 4226.69,3417.49 4573.36,3417.49 U11.1@4664.34,3508.47
  Bottom Layer w15: U11.1@4666.8,3505.1 4869.44,3302.45 7762.74,3302.45 7801.13,3340.84 7801.13,3462.63 U1-CN11.16@7852.1,3513.59
NRST: U1-CN11.14
PA1: U1-CN11.30
PA2: U2-CN12.35
PA7: U2-CN12.15
PA9: U2-CN12.21
PA10: U2-CN12.33
PA11: U2-CN12.14
PA12: U2-CN12.12
PA13: U1-CN11.13
PA14: U1-CN11.15
PA15: U1-CN11.17
PB0: U1-CN11.34
PB3: U2-CN12.31
PB5: U2-CN12.29 U4.1 | length 2936.9
  Top Layer w10: U4.1@6557.24,4685.01 6802.36,4685.01 v1@6803.57,4686.23
  Bottom Layer w10: v1(6803.57,4685.01) 7167.61,4685.01 7187.63,4705.03 7187.63,5059.97 8072.65,5059.97 8308.85,5296.17 8308.85,5529.72 8344.51,5565.37 8528.53,5565.37 8556.4,5593.23 8556.4,5804.42 U2-CN12.29@8552.76,5808.06
PB6: U2-CN12.17 U4.4 | length 2896.8
  Top Layer w10: U4.4@6562.1,4837.91 6566.95,4833.05 6844.69,4833.05 v1@6846.18,4834.54
  Bottom Layer w10: v1(6847.26,4831.03) 6847.8,4831.57 7169.63,4831.57 7169.63,5080.87 8059.69,5080.87 8290.25,5311.42 8290.25,5700.29 8260.47,5730.06 7955.34,5730.06 7949.88,5735.52 U2-CN12.17@7949.88,5813.79
PB7: U1-CN11.21
PB13: U2-CN12.30
PB14: U2-CN12.28
PC1: U1-CN11.36
PC2: U1-CN11.35
PC3: U1-CN11.37
PC4: U2-CN12.34
PC5: U2-CN12.6
PC6: U2-CN12.4
PC8: R129.2 U2-CN12.2 U4.3 | length 1719.4
  Top Layer w10: U4.3@6565.29,4785.6 6699.36,4785.6 R129.2@6710.85,4797.09 ; R129.2@6715.6,4799.05 6794.88,4799.05 v1@6796.49,4797.43 ; v1(7120.85,4801.3) 7081.22,4840.94 7081.22,5873.59 7112.36,5904.73 U2-CN12.2@7139.46,5904.73
  Bottom Layer w10: v1(6794.88,4798.24) v1@7122.51,4798.24
PC9: U2-CN12.1
PC10: C25.1 R139.1 U1-CN11.1 | length 3481.9
  Top Layer w10: C25.1@4322.32,4030.95 4368.93,3984.35 R139.1@4368.93,3886.11 ; R139.1@4366.65,3883.83 R139.1@4368.93,3886.11 ; R139.1@4368.93,3885.39 R139.1@4368.93,3886.11 ; v1(4537.34,3967.96) 4450.78,3967.96 R139.1@4368.93,3886.11
  Bottom Layer w10: v1@4537.04,3966.24 4537.88,3967.08 5594.12,3967.08 5658.27,3902.93 5658.27,3456.61 5708.04,3406.84 7086.04,3406.84 7089.44,3410.26 U1-CN11.1@7153.3,3410.26
PC11: C26.1 R140.1 U1-CN11.2 | length 3246.5
  Top Layer w10: R140.1@4709.46,3890.46 4709.46,3985.91 C26.1@4755.57,4032.03 ; C26.1@4760.21,4037.13 4760.21,4059.78 4782.86,4082.43 5674.34,4082.43 v1(5676.77,4080)
  Bottom Layer w10: v1@5676.77,4079.6 5676.27,4079.11 5676.27,3470.72 5722.14,3424.84 7064.44,3424.84 U1-CN11.2@7149.28,3509.68
PC12: U1-CN11.3
PC13: U1-CN11.23
PC14: U1-CN11.25
PC15: U1-CN11.27
PD0: U1-CN11.57
PD1: U1-CN11.55
PD2: U1-CN11.4
PD4: R130.2 U1-CN11.39 U5.3 | length 3284.9
  Top Layer w10: U5.3@6559.43,4311.7 6562.67,4314.93 6688.7,4314.93 6703.37,4329.61 6707.73,4325.25 v1(6809.09,4325.25)
  Bottom Layer w15: v1@6812.46,4323.22 6956.13,4323.22 7003.33,4276.01 7003.33,3699.85 7068.59,3634.59 8972.22,3634.59 9004.46,3602.35 9004.46,3446.91 U1-CN11.39@9034.49,3416.87
PD5: U1-CN11.41 U5.4 | length 3449
  Top Layer w10: U5.4@6563.88,4365.51 6823.07,4365.51 v1(6824.43,4366.87)
  Bottom Layer w15: v1@6827.62,4367.12 6828.1,4366.64 6988.55,4366.64 7026.33,4328.86 7026.33,3709.38 7078.12,3657.59 9083.89,3657.59 9102.09,3639.39 9102.09,3470.11 U1-CN11.41@9158.51,3413.69
PD6: U1-CN11.43 U5.1 | length 3339.7
  Top Layer w15: U5.1@6572.62,4216.39 6971.85,4216.39 v1(7062.85,4125.38)
  Bottom Layer w15: v1(7062.85,4125.38) 7062.85,3750.46 7132.72,3680.59 9153.54,3680.59 9202.5,3631.63 9202.5,3461.32 U1-CN11.43@9257.41,3406.41
PD7: U1-CN11.45
PD8: U2-CN12.10
PD9: U1-CN11.69
PD10: U2-CN12.65
PD14: U2-CN12.46
PD15: U2-CN12.48
PE1: U1-CN11.61
PE2: U1-CN11.46
PE3: U1-CN11.47
PE4: U1-CN11.48
PE5: U1-CN11.50
PE9: U2-CN12.52
PE11: U2-CN12.56
PE13: U2-CN12.55
PF0: U1-CN11.53
PF1: U1-CN11.51
PF2: U1-CN11.52
PF3: U2-CN12.58
PF6: U1-CN11.9 U9.1 | length 1563.3
  Top Layer w10: U9.1@6543.7,3703.28 6543.7,3287.88 6557.85,3273.72 7529.02,3273.72 7550.86,3295.56 7550.86,3414.48 U1-CN11.9@7555.71,3419.33
PF7: U1-CN11.11 U9.4 | length 1502.2
  Top Layer w10: U9.4@6550.53,3859.88 6806.16,3859.88 v1@6811.01,3864.74
  Bottom Layer w10: v1(6808.59,3861.5) 6808.59,3620.43 6847.42,3581.6 7373.24,3581.6 7399.94,3554.9 7399.94,3456.21 7611.08,3456.21 7653.96,3413.33 U1-CN11.11@7653.96,3403.63
PF8: R136.2 U1-CN11.54 U9.3 | length 4204
  Top Layer w10: U9.3@6513.36,3810.06 6492.33,3789.03 6492.33,3272.91 6518.21,3247.02 9671.77,3247.02 9699.47,3274.72 9699.47,3460.79 U1-CN11.54@9757.71,3519.04 ; U9.3@6546.32,3812.8 6698.59,3812.8 R136.2@6704.34,3818.54
PF9: U1-CN11.56
PF12: U2-CN12.59
PF13: U2-CN12.57 U36.3 | length 4466.9
  Top Layer w10: U36.3@7537.73,7617.03 7530.45,7609.75 7530.45,7185.65 7757.97,7185.65 7810.76,7132.87 7810.76,6685.11 v1@7807.12,6681.47 ; v1@9903.11,6300.1 9903.11,5839.57 U2-CN12.57@9934.9,5807.78
  Bottom Layer w10: v1(7810.76,6681.47) 9950.3,6681.47 9996.55,6635.22 9996.55,6585.06 9953.67,6542.19 9817.77,6542.19 9817.77,6314.26 9833.48,6298.55 v1@9903.59,6298.55
  other v1: 9902.78,6299.36
PF14: U2-CN12.50
PF15: U2-CN12.60
PG0: U1-CN11.59
PG1: U1-CN11.58
PG4: U2-CN12.69
PG7: U2-CN12.67
PG11: U1-CN11.70
PG13: U1-CN11.68
PG14: U2-CN12.61
PH0: U1-CN11.29
PH1: U1-CN11.31
SW2-: R139.2 R141.2 U10.2 | length 481
  Top Layer w10: R141.2@4226.69,3834.08 4355.97,3834.08 R139.2@4365.07,3824.98 ; R139.2@4365.07,3833.36 R139.2@4365.07,3824.98 ; R139.2@4365.55,3824.5 R139.2@4365.07,3824.98 ; U10.2@4387.33,3504.4 4365.07,3526.67 R139.2@4365.07,3824.98
SW3-: R140.2 R142.2 U11.2 | length 448
  Top Layer w10: R140.2@4718.92,3831.2 4834.8,3831.2 R142.2@4842.46,3838.86 ; R142.2@4851.08,3827.37 4873.11,3805.35 U11.2@4873.11,3515.18
VBAT: U1-CN11.33
VCC: U7.3 U33.1 | length 668.4
  Top Layer w20: U7.3@3518.41,8143.97 3525.59,8136.78 4180.23,8136.78 U33.1@4182.8,8139.35
VIN: U1-CN11.24
VM1-A: R132.1 R134.2 U5.6 U6.1 | length 8534.3
  Top Layer w10: R132.1@6177.37,4388.03 6176.6,4388.8 6176.6,4446.57 6240.77,4510.74 6357.6,4510.74 R134.2@6393.35,4474.98 ; R132.1@6181.63,4387.77 6181.63,4325.2 6190.57,4316.27 U5.6@6342.52,4316.27
  Top Layer w15: v1@5981.59,4552.32 6013.08,4552.32 R132.1@6176.6,4388.8
  Bottom Layer w15: U6.1@4112.41,8795.8 3970.43,8653.83 3276.93,8653.83 3215.87,8592.78 3215.87,6503.16 3289.24,6429.79 3751.52,6429.79 3800.45,6380.86 3800.45,4583.34 3871.76,4512.03 5940.24,4512.03 v1@5979.16,4550.96
  other v1: 5976.87,4550.06
VM1-B: R128.1 R132.2 U5.7 U6.2 | length 8396.2
  Top Layer w10: v1(5941.36,4588.77) 5943.59,4586.54 5943.59,4467.42 6030.14,4380.86 R132.2@6113.4,4380.86 ; R128.1@6108.85,4264.55 6115.87,4271.57 R132.2@6115.87,4390.96 ; R128.1@6122.26,4267.74 6325.92,4267.74 U5.7@6329.11,4264.55
  Bottom Layer w15: U6.2@4325.37,8768.5 4172.47,8615.61 3293.46,8615.61 3243.58,8565.72 3243.58,6521.53 3304.38,6460.73 3768.73,6460.73 3825.73,6403.73 3825.73,4658.26 3893.28,4590.71 5939.42,4590.71 v1(5941.36,4588.77)
VM2+: D1.1 D2.1 D3.1 D4.1 D5.1 D6.1 D7.1 D8.1 D9.1 D10.1 D11.1 D12.1 D13.1 D14.1 D15.1 D16.1 D17.1 D18.1 D19.1 D20.1 D21.1 R143.2 U8.3 | length 7193.8
  Top Layer w15: U8.3@3522.59,7062.23 3526.7,7058.12 4174.89,7058.12 4205.79,7089.01 R143.2@4205.79,7483.31 4205.79,7778.87 4260.93,7834.01 D1.1@4410.46,7834.01 D2.1@4689.39,7834.01 D3.1@4968.33,7834.01 D4.1@5247.27,7834.01 D5.1@5526.2,7834.01 D6.1@5805.14,7834.01 D7.1@6084.08,7834.01 D8.1@6363.02,7834.01 D9.1@6641.95,7834.01 D10.1@6920.89,7834.01 D11.1@7199.83,7834.01 D12.1@7478.76,7834.01 D13.1@7757.7,7834.01 D14.1@8036.64,7834.01 D15.1@8315.58,7834.01 D16.1@8594.51,7834.01 D17.1@8873.45,7834.01 D18.1@9152.39,7834.01 D19.1@9431.32,7834.01 D20.1@9710.26,7834.01 D21.1@9989.2,7834.01
VM2-A: R137.1 R138.2 U8.1 U9.6 | length 6378.7
  Top Layer w10: U8.1@3526.68,6664.61 3562.17,6629.12 3562.17,6346.12 v1@3556.47,6340.42 ; v1@5987.13,4012.45 6068.82,4012.45 6171.31,3909.95 6171.31,3944.43 6230.69,4003.81 6358.06,4003.81 R138.2@6395.4,3966.46 ; R137.1@6175.98,3898.25 6263.6,3810.63 U9.6@6319.62,3810.63
  Bottom Layer w10: v1(3559.99,6340.52) 3554.6,6335.13 3331.43,6335.13 3289.08,6292.77 3289.08,4145.45 3321.73,4112.8 4279.22,4112.8 4355.67,4189.25 5943.95,4189.25 5986.65,4146.54 5986.65,4014.34 v1(5987.74,4013.26)
VM2-B: R135.1 R137.2 U8.2 U9.7 | length 6572.7
  Top Layer w10: U8.2@3525.61,6865.89 3640.89,6750.62 3640.89,6379.83 v1@3640.67,6379.61 ; v1@5987.13,3968.76 6052.1,3968.76 6124.48,3896.39 R135.1@6124.48,3780.52 ; R135.1@6124.48,3778.6 6141.71,3761.36 U9.7@6331.33,3761.36
  Bottom Layer w10: v1(3641.65,6379.62) 3307.5,6379.62 3271.08,6343.2 3271.08,4133.39 3309.66,4094.8 4286.68,4094.8 4363.12,4171.25 5936.49,4171.25 5956.36,4151.38 5956.36,3985.19 5973.6,3967.95 v1(5987.74,3967.95)
VREFP: U2-CN12.7
"": U1-CN11.10 U1-CN11.26 U1-CN11.67

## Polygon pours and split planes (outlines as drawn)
GND on Top Layer (solid, remove dead copper, pour order 0): 3082.89,3000 11136.46,3000 11136.46,9100.07 3082.89,9100.07
GND on Bottom Layer (solid, remove dead copper, pour order 1): 3000,3038.74 11164.15,3038.74 11164.15,9184.89 3000,9184.89

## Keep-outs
Board Outline Layer:
  lines w10 net "": 3164.32,3176.23 ccw(c3223.37,3176.23) 3223.37,3117.17 10979.28,3117.17 ccw(c10979.28,3176.23) 11038.33,3176.23 11038.33,8963.63 ccw(c10979.28,8963.63) 10979.28,9022.68 3223.37,9022.68 ccw(c3223.37,8963.63) 3164.32,8963.63 3164.32,3176.23
Multi-Layer:
  region net "": 3424.16,8825.83 ccw(c3361.16,8825.83) 3298.17,8825.83 ccw(c3361.16,8825.83)
  region net "": 10904.47,8825.83 ccw(c10841.48,8825.57) 10778.49,8825.83 ccw(c10841.48,8826.1)
  region net "": 3424.16,3314.02 ccw(c3361.16,3314.02) 3298.17,3314.02 ccw(c3361.16,3314.02)
  region net "": 10904.47,3314.02 ccw(c10841.48,3313.76) 10778.49,3314.02 ccw(c10841.48,3314.28)

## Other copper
Top Layer:
  drawing of 1153 lines, arcs and shapes, not listed
Bottom Layer:
  drawing of 241 lines, arcs and shapes, not listed

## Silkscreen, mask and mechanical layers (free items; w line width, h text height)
Top Silkscreen Layer:
  lines w10 net "": 3610.77,3712.52 3881.87,3712.52 3881.87,3791.26 3610.77,3791.26 3610.77,3712.52 ; 3783.58,3327.8 3862.32,3327.8 3862.32,3567.95 3783.58,3567.95 3783.58,3327.8 ; 3809.93,7630.37 4050.08,7630.37 4050.08,7709.11 3809.93,7709.11 3809.93,7630.37 ; 3809.93,7732.73 4050.08,7732.73 4050.08,7811.47 3809.93,7811.47 3809.93,7732.73 ; 3811.24,7833.9 4051.4,7833.9 4051.4,7912.64 3811.24,7912.64 3811.24,7833.9 ; 3811.89,7941.39 4052.05,7941.39 4052.05,8020.13 3811.89,8020.13 3811.89,7941.39 ; 3813.86,6546.47 4054.02,6546.47 4054.02,6625.21 3813.86,6625.21 3813.86,6546.47 ; 3813.86,6648.83 4054.02,6648.83 4054.02,6727.57 3813.86,6727.57 3813.86,6648.83 ; 3815.17,6750 4055.33,6750 4055.33,6828.74 3815.17,6828.74 3815.17,6750 ; 3815.83,6857.49 4055.99,6857.49 4055.99,6936.23 3815.83,6936.23 3815.83,6857.49 ; 3888.41,3327.8 3967.15,3327.8 3967.15,3567.95 3888.41,3567.95 3888.41,3327.8 ; 3896.54,3711.92 4156.72,3711.92 4156.72,3790.66 3896.54,3790.66 3896.54,3711.92 ; 4154.5,7726.02 4233.24,7726.02 4233.24,7966.18 4154.5,7966.18 4154.5,7726.02 ; 4159.96,8199.26 4238.7,8199.26 4238.7,8439.42 4159.96,8439.42 4159.96,8199.26 ; 4931.9,8580.69 5010.64,8580.69 5010.64,8820.85 4931.9,8820.85 4931.9,8580.69 ; 5013.92,8579.5 5092.66,8579.5 5092.66,8819.66 5013.92,8819.66 5013.92,8579.5 ; 5035.52,3335.67 5114.26,3335.67 5114.26,3575.83 5035.52,3575.83 5035.52,3335.67 ; 5099.22,8580.69 5177.96,8580.69 5177.96,8820.85 5099.22,8820.85 5099.22,8580.69 ; 5139.55,3335.67 5218.29,3335.67 5218.29,3575.83 5139.55,3575.83 5139.55,3335.67 ; 5185.84,8580.69 5264.58,8580.69 5264.58,8820.85 5185.84,8820.85 5185.84,8580.69 ; 5920.22,3374.6 5998.96,3374.6 5998.96,3532.08 5920.22,3532.08 5920.22,3374.6 ; 6026.52,3375.04 6105.26,3375.04 6105.26,3532.52 6026.52,3532.52 6026.52,3375.04 ; 7130.4,4044.75 7421.63,4044.75 7421.63,5295.15 7130.4,5295.15 7130.4,4044.75 ; 7300.99,7264.01 7379.73,7264.01 7379.73,7504.17 7300.99,7504.17 7300.99,7264.01 ; 7386.29,7265.2 7465.03,7265.2 7465.03,7505.36 7386.29,7505.36 7386.29,7265.2 ; 7472.91,7265.2 7551.65,7265.2 7551.65,7505.36 7472.91,7505.36 7472.91,7265.2 ; 10422.83,7886.4 10662.99,7886.4 10662.99,7965.14 10422.83,7965.14 10422.83,7886.4 ; 10426.47,8048.4 10721.24,8048.4 10721.24,8127.14 10426.47,8127.14 10426.47,8048.4 ; 10431.93,8235.88 10719.42,8235.88 10719.42,8314.62 10431.93,8314.62 10431.93,8235.88
  text "VM1-A" at 4947.44,8812.97 h45.43 r270
  text "VM1-B" at 5029.46,8811.78 h45.43 r270
  text "VM1+" at 5114.76,8810.97 h45.43 r270
  text "VM1-" at 5201.38,8810.97 h45.43 r270
  text "Vcc" at 4175.5,8427.55 h45.43 r270
  text "D21-5V" at 10441.55,8255.2 h45.43
  text "D21-3V3" at 10419.54,8065.91 h45.43
  text "AM1-A" at 3819.77,7956.93 h45.43
  text "5V" at 4170.04,7952.31 h45.43 r270
  text "GND" at 10423.88,7903.91 h45.43
  text "AM1-B" at 3819.12,7849.44 h45.43
  text "AM1+" at 3819.8,7748.27 h45.43
  text "AM1-" at 3819.8,7645.9 h45.43
  text "PF13" at 7488.45,7495.48 h45.43 r270
  text "GND" at 7401.83,7493.49 h45.43 r270
  text "5V" at 7316.53,7490.31 h45.43 r270
  text "VM2-A" at 3812.88,6875 h45.43
  text "VM2-B" at 3812.88,6768.7 h45.43
  text "VM2+" at 3814.88,6664.37 h45.43
  text "VM2-" at 3814.88,6562.01 h45.43
  text "MDIO-BOARD (H723ZG) /  YC Rev.1 May.26.24\"" at 4245.61,4256.75 h86.82
  text "Nucleo-144 H723ZG /  Top Side" at 7363.99,3955.62 h86.82 r90
  text "LED21+" at 3616.65,3728.06 h45.43
  text "LED21-" at 3902.42,3727.46 h45.43
  text "5V" at 5983.42,3388.46 h45.43 r90
  text "GND" at 6089.72,3386.91 h45.43 r90
  text "SW3+" at 5098.72,3345.54 h45.43 r90
  text "SW3-" at 5202.75,3345.54 h45.43 r90
  text "SW2+" at 3846.78,3337.67 h45.43 r90
  text "SW2-" at 3951.61,3337.67 h45.43 r90
Mechanical Layer:
  circle w1 net "": c3361.17,8825.83 r62.99
  circle w1 net "": c10841.48,8825.83 r62.99
  circle w1 net "": c3361.17,3314.02 r62.99
  circle w1 net "": c10841.48,3314.02 r62.99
